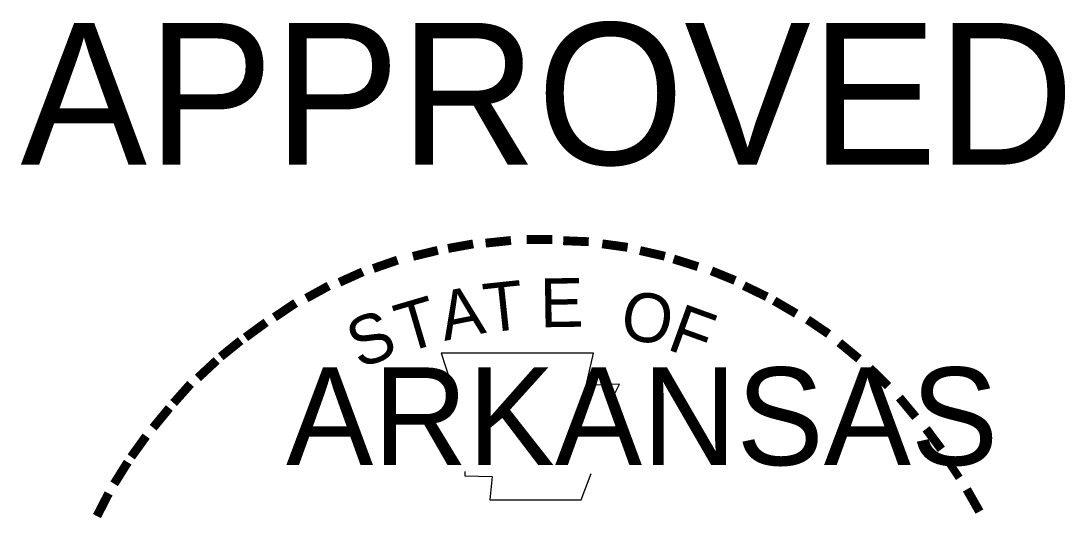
# Model space of a CAD drawing. Extents: x 1671357 to 13005564, y 567358 to 14261451.
# Drawn here: x 12758328.665 to 12758331.239, y 14259943.128 to 14259944.355 of the extents above; entities that cross this region are included whole.
import ezdxf

# ---------------------------------------------------------------- set-up
doc = ezdxf.new("R2010")
doc.units = 0
doc.layers.add('1', color=7, linetype='Continuous')
doc.layers.add('Default', color=7, linetype='Continuous')

msp = doc.modelspace()

# ---------------------------------------------------------------- linework, layer by layer
at = {"layer": '1'}
for points in [[(12758329.7008, 14259943.535), (12758329.7333, 14259943.4361)], [(12758330.1239, 14259943.4241), (12758330.1407, 14259943.459), (12758330.0588, 14259943.4554), (12758330.0769, 14259943.535), (12758329.7008, 14259943.535)], [(12758329.7598, 14259943.2433), (12758329.7598, 14259943.2324), (12758329.8273, 14259943.2312), (12758329.8213, 14259943.1734), (12758330.0467, 14259943.1734), (12758330.0708, 14259943.2384)]]:
    msp.add_lwpolyline(points, dxfattribs=at)

# ---------------------------------------------------------------- texts
for s, height, rotation, p in [('-', 0.1929, 5.8968, (12758329.8069, 14259943.7314)), ('-', 0.1928, 0.1862, (12758329.9009, 14259943.7411)), ('-', 0.1928, 357.743, (12758329.9877, 14259943.7387)), ('-', 0.1929, 13.6302, (12758329.6381, 14259943.6989)), ('-', 0.1929, 10.2193, (12758329.7201, 14259943.7182)), ('-', 0.1929, 352.1617, (12758330.0769, 14259943.7327)), ('-', 0.1929, 347.2049, (12758330.1637, 14259943.7182)), ('-', 0.1928, 19.1761, (12758329.5477, 14259943.67)), ('-', 0.1929, 342.3362, (12758330.2408, 14259943.7001)), ('-', 0.1928, 24.3072, (12758329.4706, 14259943.6374)), ('-', 0.1929, 337.8551, (12758330.3288, 14259943.6736)), ('T', 0.1205, 6.0228, (12758329.8117, 14259943.5856)), ('E', 0.1205, 0.8323, (12758329.9455, 14259943.5989)), ('-', 0.1928, 28.7918, (12758329.3946, 14259943.6001)), ('A', 0.1205, 11.2132, (12758329.7092, 14259943.5651)), ('O', 0.1205, 350.4515, (12758330.1383, 14259943.5735)), ('-', 0.1928, 334.1211, (12758330.4047, 14259943.6398)), ('-', 0.1929, 34.0636, (12758329.3223, 14259943.5555)), ('T', 0.1205, 16.4036, (12758329.6104, 14259943.535)), ('-', 0.1929, 329.6409, (12758330.4746, 14259943.6061)), ('S', 0.1205, 21.594, (12758329.4995, 14259943.4952)), ('F', 0.1205, 340.0707, (12758330.2541, 14259943.5458)), ('-', 0.1929, 36.2317, (12758329.2536, 14259943.5072)), ('-', 0.1929, 325.8627, (12758330.553, 14259943.5627)), ('-', 0.1928, 38.9507, (12758329.1957, 14259943.4614)), ('-', 0.1929, 320.5297, (12758330.6265, 14259943.5109)), ('-', 0.1929, 42.9622, (12758329.1439, 14259943.412)), ('-', 0.1929, 315.5786, (12758330.6976, 14259943.453)), ('-', 0.1929, 48.4231, (12758329.0897, 14259943.3542)), ('-', 0.1929, 309.8797, (12758330.7663, 14259943.3867)), ('-', 0.1929, 50.6142, (12758329.0414, 14259943.2951)), ('-', 0.1929, 306.6522, (12758330.8302, 14259943.3132)), ('-', 0.1929, 54.2325, (12758328.9908, 14259943.2264)), ('-', 0.1688, 303.6753, (12758330.8881, 14259943.2457)), ('-', 0.1928, 58.0706, (12758328.9522, 14259943.1637)), ('-', 0.1929, 299.6684, (12758330.9267, 14259943.1721)), ('-', 0.1929, 62.8713, (12758328.9137, 14259943.089))]:
    msp.add_text(s, height=height, rotation=rotation, dxfattribs=at).set_placement(p)
msp.add_text('ARKANSAS', height=0.24108, dxfattribs=at).set_placement((12758329.3187, 14259943.2589))
at = {"layer": 'Default'}
msp.add_text('APPROVED', height=0.34956, dxfattribs=at).set_placement((12758328.6641, 14259944.0003))

doc.saveas('drawing.dxf')
